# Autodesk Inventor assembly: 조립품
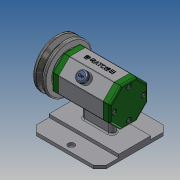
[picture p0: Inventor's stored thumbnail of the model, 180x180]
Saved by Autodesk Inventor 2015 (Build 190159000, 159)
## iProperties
Created: 2018-06
Part Number: 조립품
Document SubType Name: Assembly
Designer: 임동건
Author: 임동건
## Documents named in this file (16)
- C:\Users\Administrator\Desktop\480608V1019\조립품.iam
- C:\Users\Administrator\Desktop\480608V1019\본체.ipt
- C:\Users\Administrator\Desktop\480608V1019\베어링 15x32x9.ipt
- C:\Users\Administrator\Desktop\480608V1019\뒤커버.ipt
- C:\Users\Administrator\Desktop\480608V1019\앞커버.ipt
- C:\Users\Administrator\Desktop\480608V1019\오일 실 15 25 7.ipt
- C:\Users\Administrator\Desktop\480608V1019\볼트 M4x12.ipt
- C:\Users\Administrator\Desktop\480608V1019\축.ipt
- C:\Users\Administrator\Desktop\480608V1019\키 3x3x12.ipt
- 키 3x3x12.ipt
- C:\Users\Administrator\Desktop\480608V1019\V벨트풀리.ipt
- C:\Users\Administrator\Desktop\480608V1019\와셔 8x17.ipt
- C:\Users\Administrator\Desktop\480608V1019\스프링와셔 8.ipt
- C:\Users\Administrator\Desktop\480608V1019\너트 M8.ipt
- 너트 M8.ipt
- C:\Users\Administrator\Desktop\480608V1019\고무캡.ipt
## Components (2 placed, 2 different names)
1. V벨트풀리:1 — 각도:10
2. 고무캡:1
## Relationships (1: Angle 1)
- 각도:10 [Angle]: V벨트풀리:1
